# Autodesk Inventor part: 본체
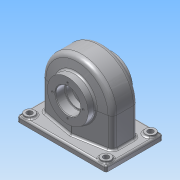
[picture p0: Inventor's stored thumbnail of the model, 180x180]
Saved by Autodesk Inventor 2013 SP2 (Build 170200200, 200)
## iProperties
Created: 2025-05
Part Number: 본체
Material: 알루미늄 6061
Document SubType Name: Modeling
Designer: a
Density: 2.71 g/cm^3
Mass: 734.294 g
Surface Area: 905.47 cm^2
Volume: 270.957 cm^3
Author: a
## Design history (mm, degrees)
sketch "스케치4"
  geometry: L1 (72, 46)-(-72, 46); L2 (-72, 46)-(-72, -46); L3 (-72, -46)-(72, -46); L4 (72, -46)-(72, 46); L5 (72, 46)-(-72, -46); L6 (-72, 46)-(72, -46); 1 further point
  constraints: 12 end point, 2 midpoint, 2 parallel, 1 horizontal, 1 perpendicular
  dimensions: "d7" = 92 distance of L1.end L2.end; "d9" = 144 distance of L1.start L1.end
extrude "돌출1" new body sketch "스케치4" distance "d10" = 9; taper "d11" = 0 deg
sketch "스케치5"
  geometry: L1 (-72, 46)-(-72, -46) reference; L2 (-57, 20)-(0, 30.051); L3 (0, 30.051)-(57, 20); L4 (57, 20)-(57, -20); L5 (57, -20)-(0, -30.051); L6 (0, -30.051)-(-57, -20); L7 (-57, -20)-(-57, 20); L8 (-54.903, 0)-(57, 0); 1 further point
  constraints: 14 end point, 2 parallel, 2 vertical alignment, 1 midpoint
  dimensions: "d12" = 20 deg angle of L5 L3; "d13" = 20 deg angle of L6 L2; "d14" = 40 distance of L3.end L4.end; "d16" = 40 distance of L6.end L2.start; "d17" = 114 distance between parallel lines of L4 L7; "d18" = 20 vertical distance of point (0, 0) L3.end; "d19" = 20 vertical distance of point (0, 0) L2.start; "d20" = 10 deg angle of L8 L3; "d21" = 10 deg angle of L8 L2
extrude "돌출2" join sketch "스케치5" distance "d22" = 48; taper "d23" = 0 deg
sketch "스케치6"
  geometry: L1 (0, 30.051)-(-57, 20) reference; L2 (-57, 20)-(-57, -20) reference; L3 (-57, -20)-(0, -30.051) reference; L4 (57, -20)-(57, 20) reference; L5 (0, 30.051)-(0, -30.051); 1 further point
  constraints: 2 end point, 1 parallel
revolve "회전1" sketch "스케치6" stored, may be unused: angle "d27" = 90 deg
fillet "모깎기2" dims "d28" = 8
feature "쉘2" dims "d29" = 12, "d30" = 5
node "작업 평면1"
sketch "스케치8"
  geometry: C1 r 24 at (0, 60); 1 further point
  constraints: 1 centre point, 1 vertical alignment
  dimensions: "d32" = 48 diameter of C1; "d34" = 60 distance of point (0, 0) C1.centre
extrude "돌출3" join sketch "스케치8" stored distance "d35" = 10; taper "d36" = 0 deg
node "작업 평면2"
sketch "스케치9"
  geometry: L1 (-72, 0)-(72, 0) reference; C1 r 33 at (0, 60); 2 further points
  constraints: 1 centre point, 1 midpoint, 1 vertical alignment
  dimensions: "d38" = 66 diameter of C1; "d40" = 60 distance from line of L1 C1.centre
extrude "돌출4" join sketch "스케치9" stored distance "d41" = 10; taper "d42" = 0 deg
sketch "스케치10"
  geometry: L1 (0, 46)-(9, 46) reference; L2 (9, 46)-(9, 30.051) reference; L3 (9, 30.051)-(27, 30.051) reference; L4 (27, 30.051)-(27, 36) reference; L5 (27, 36)-(93, 36) reference; L6 (93, 36)-(93, 23.703) reference; L7 (93, 23.703)-(107.389, 21.166) reference; L8 (114, 13.287)-(114, -13.287) reference; L9 (107.389, -21.166)-(93, -23.703) reference; L10 (93, -23.703)-(93, -36) reference; L11 (93, -36)-(27, -36) reference; L12 (27, -36)-(27, -30.051) reference; L13 (27, -30.051)-(9, -30.051) reference; L14 (9, -30.051)-(9, -46) reference; L15 (9, -46)-(0, -46) reference; L16 (0, -46)-(0, -24.974) reference; L17 (0, -24.974)-(36, -24.974) reference; L18 (36, -24.974)-(36, -12) reference; L19 (36, -12)-(84, -12) reference; L20 (84, -12)-(84, -20.213) reference; L21 (84, -20.213)-(106.521, -16.242) reference; L22 (109, -13.287)-(109, 13.287) reference; L23 (106.521, 16.242)-(84, 20.213) reference; L24 (84, 20.213)-(84, 12) reference; L25 (84, 12)-(36, 12) reference; L26 (36, 12)-(36, 24.974) reference; L27 (36, 24.974)-(0, 24.974) reference; L28 (0, 24.974)-(0, 46) reference; L29 (80, 36)-(80, 21.6); L30 (79.4, 21)-(77.5, 21); L31 (77.5, 21)-(77.5, -21); L32 (77.5, -21)-(79.4, -21); L33 (80, -21.6)-(80, -36); L34 (60, -36)-(60, 36); L35 (80, 36)-(60, 36); L36 (80, -36)-(60, -36); A1 r 8 centre (106, 13.287) between (114, 13.287) and (107.389, 21.166) reference; A2 r 8 centre (106, -13.287) between (107.389, -21.166) and (114, -13.287) reference; A3 r 3 centre (106, -13.287) between (106.521, -16.242) and (109, -13.287) reference; A4 r 3 centre (106, 13.287) between (109, 13.287) and (106.521, 16.242) reference; A5 r 0.6 centre (79.4, 21.6) between (79.4, 21) and (80, 21.6); A6 r 0.6 centre (79.4, -21.6) between (80, -21.6) and (79.4, -21); 3 further points
  constraints: 16 end point, 6 point on line, 4 parallel, 4 point on circle, 4 tangent, 3 perpendicular, 2 centre point, 2 midpoint, 1 collinear, 1 equal radius
  dimensions: "d43" = 120 diameter of point (0, 0) L34; "d44" = 40 diameter of L33 L34; "d45" = 35 diameter of L31 L34; "d46" = 15 distance of point (80, -21) L33.end; "d47" = 15 distance of L29.start point (80, 21); "d48" = 0.6 radius of A5
revolve "회전2" sketch "스케치10" stored, may be unused: angle "d49" = 90 deg
chamfer "모따기1" distance "d50" = 1; stored, may be unused: second distance "d51" = 2, angle "d52" = 45 deg
sketch "스케치11" dims "d53" = 50
  geometry: L1 (0, 0)-(0, 25); C1 r 21 at (0, 0) reference; 2 further points
  constraints: 2 coincident, 2 end point, 1 vertical, 1 vertical alignment, 2 other
hole "구멍1" sketch "스케치11" at (0, 25) diameter "d55" = 3.242; stored, may be unused: countersink angle "d59" = 90 deg, drill point angle "d61" = 118 deg; dims "d56" = 8, "d57" = 4, "d58" = 2, "d60" = 10
sketch "스케치12"
  geometry: C1 r 8 at (62, 36); C2 r 8 at (62, -36); C3 r 8 at (-62, 36); C4 r 8 at (-62, -36); 1 further point
  constraints: 4 centre point, 2 horizontal alignment, 2 vertical alignment
  dimensions: "d65" = 72 distance of C2.centre C1.centre; "d67" = 124 distance of C1.centre C3.centre; "d68" = 16 diameter of C1; "d69" = 16 diameter of C3; "d70" = 16 diameter of C4; "d71" = 16 diameter of C2; "d72" = 36 vertical distance of C1.centre point (0, 0); "d73" = 62 horizontal distance of point (0, 0) C3.centre
extrude "돌출5" join sketch "스케치12" distance "d74" = 3; taper "d75" = 0 deg
hole "구멍2" diameter "d78" = 9; stored, may be unused: countersink angle "d82" = 90 deg, drill point angle "d84" = 118 deg; dims "d79" = 9, "d80" = 4, "d81" = 2, "d83" = 10, "d85" = 10, "d86" = 10
hole "구멍3" diameter "d89" = 9; stored, may be unused: countersink angle "d93" = 90 deg, drill point angle "d95" = 118 deg; dims "d87" = 10, "d88" = 10, "d90" = 9, "d91" = 4, "d92" = 2, "d94" = 10
hole "구멍4" diameter "d98" = 9; stored, may be unused: countersink angle "d102" = 90 deg, drill point angle "d104" = 118 deg; dims "d96" = 10, "d97" = 10, "d99" = 9, "d100" = 4, "d101" = 2, "d103" = 10
hole "구멍5" diameter "d107" = 9; stored, may be unused: countersink angle "d111" = 90 deg, drill point angle "d113" = 118 deg; dims "d105" = 10, "d106" = 10, "d108" = 9, "d109" = 4, "d110" = 2, "d112" = 10
fillet "모깎기3" dims "d114" = 3
fillet "모깎기4" dims "d115" = 3
fillet "모깎기5" dims "d116" = 3
fillet "모깎기6" dims "d117" = 3
node "솔리드1"
mirror "대칭1"
pattern_circular "원형 패턴1" dims angle "d63" = 360 deg
mirror "대칭2"
node "절단 모서리 투영2"
other parameters: "d31" = 12, "d37" = 36
